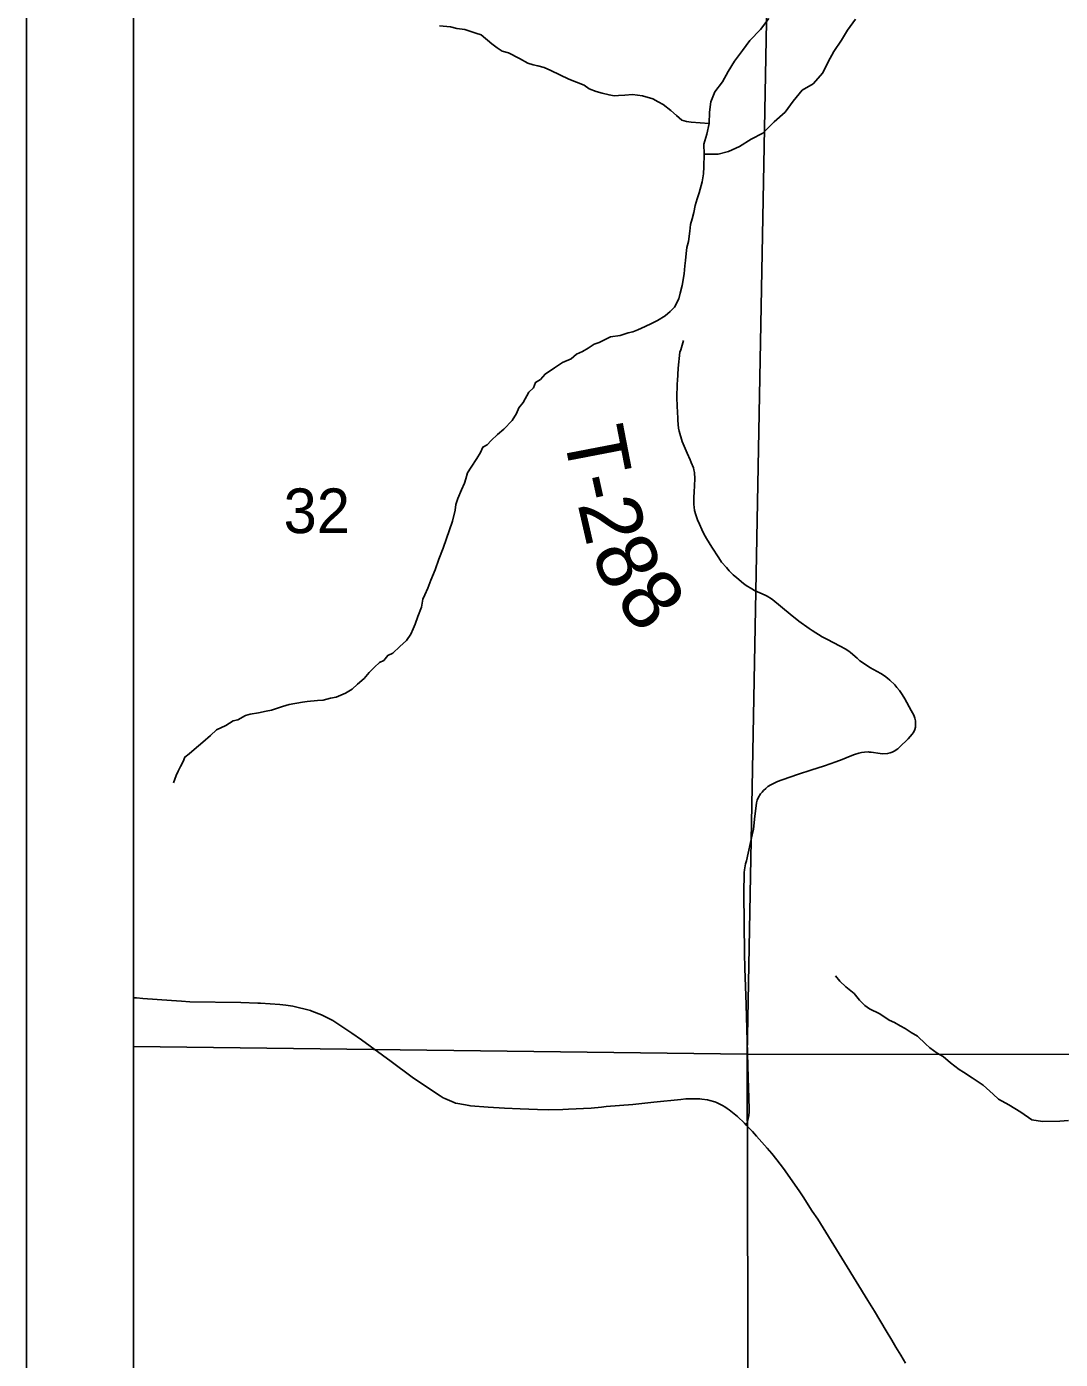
# Model space of a CAD drawing. Extents: x 0 to 34, y 0 to 22.
# Drawn here: x 18.5 to 19.467, y 15.38 to 16.628 of the extents above; entities that cross this region are included whole.
import ezdxf

# ---------------------------------------------------------------- set-up
doc = ezdxf.new("R2010")
doc.units = 0
for name, color, linetype in [('GM_X_Corporation', 7, 'Continuous'), ('GM_X_County_Road', 7, 'Continuous'), ('GM_X_Major_Lake', 7, 'Continuous'), ('GM_X_Minor_River', 7, 'Continuous'), ('GM_X_Section_Text', 7, 'Continuous'), ('GM_X_Township_Road', 7, 'Continuous'), ('GM_X_Township_Road_Text', 7, 'Continuous'), ('SH_Data', 7, 'Continuous')]:
    doc.layers.add(name, color=color, linetype=linetype)

msp = doc.modelspace()

# ---------------------------------------------------------------- linework, layer by layer
at = {"layer": 'GM_X_Corporation'}
for points in [[(18.6, 19.2331), (18.6, 14.6606), (18.9216, 14.6592), (19.4007, 14.6554), (19.8855, 14.6528), (20.2016, 14.6512), (20.203, 14.81), (20.1987, 15.2691), (20.2208, 16.9558), (20.2471, 18.8539), (20.254, 19.2058), (20.065, 19.208), (18.9898, 19.2261)], [(18.6, 16.7037), (18.6, 15.673), (19.1743, 15.6658), (19.1937, 16.6992)], [(19.1937, 16.6992), (20.2179, 16.6698), (20.1931, 15.6647), (19.1743, 15.6658)], [(18.6, 15.673), (18.6, 14.6612), (19.1768, 14.6588), (19.1743, 15.6658)], [(20.1931, 15.6647), (20.2028, 14.6536), (19.1768, 14.6588), (19.1743, 15.6658)]]:
    msp.add_lwpolyline(points, close=True, dxfattribs=at)
at = {"layer": 'GM_X_County_Road'}
msp.add_lwpolyline([(18.6, 15.7185), (18.6029, 15.7184), (18.6087, 15.7179), (18.6357, 15.7158), (18.645, 15.7152), (18.6528, 15.7148), (18.7003, 15.7142), (18.7165, 15.7135), (18.7187, 15.7134), (18.7368, 15.7121), (18.7426, 15.7115), (18.7469, 15.711), (18.749, 15.7105), (18.7656, 15.7065), (18.7669, 15.706), (18.7759, 15.7026), (18.7817, 15.6996), (18.7865, 15.6971), (18.7883, 15.6959), (18.8043, 15.6853), (18.8133, 15.679), (18.8411, 15.6589), (18.8609, 15.6443), (18.8677, 15.6395), (18.887, 15.6266), (18.8898, 15.6249), (18.8915, 15.6241), (18.9, 15.6205), (18.9014, 15.6199), (18.9036, 15.6195), (18.914, 15.6176), (18.9155, 15.6174), (18.9318, 15.6161), (18.9472, 15.6152), (18.962, 15.6145), (18.9781, 15.6139), (18.9888, 15.6137), (19.0018, 15.6138), (19.0072, 15.6141), (19.0282, 15.6152), (19.038, 15.6161), (19.0425, 15.6166), (19.0672, 15.6187), (19.0869, 15.6209), (19.1122, 15.6234), (19.1169, 15.6238), (19.1249, 15.624), (19.1301, 15.624), (19.1319, 15.6237), (19.1371, 15.623), (19.1393, 15.6224), (19.144, 15.6211), (19.1455, 15.6205), (19.1512, 15.6177), (19.1533, 15.6164), (19.1557, 15.6148), (19.1575, 15.6135), (19.1652, 15.6072), (19.1717, 15.6012), (19.1734, 15.5992), (19.1756, 15.5972), (19.1792, 15.5934), (19.1832, 15.5891), (19.1931, 15.5777), (19.1974, 15.5726), (19.202, 15.5667), (19.2083, 15.5586), (19.2231, 15.5377), (19.2268, 15.5321), (19.2352, 15.5188), (19.2403, 15.5112), (19.2655, 15.4706), (19.2872, 15.4352), (19.2934, 15.4251), (19.3045, 15.4066), (19.3096, 15.3979), (19.3136, 15.3913), (19.318, 15.3838), (19.3224, 15.3765)], dxfattribs=at)
at = {"layer": 'GM_X_Major_Lake'}
msp.add_lwpolyline([(19.1947, 16.6352), (19.1868, 16.6249), (19.1769, 16.6147), (19.1701, 16.6052), (19.1626, 16.5953), (19.1565, 16.5854), (19.1512, 16.576), (19.144, 16.5665), (19.1402, 16.557), (19.1391, 16.5475), (19.1387, 16.5369), (19.1365, 16.527), (19.1338, 16.5175), (19.1342, 16.508), (19.1471, 16.508), (19.1569, 16.5107), (19.1671, 16.5153), (19.1781, 16.5221), (19.1891, 16.5278), (19.1997, 16.5384), (19.2099, 16.5476), (19.2175, 16.5578), (19.2258, 16.5681), (19.236, 16.5741), (19.2451, 16.5844), (19.25, 16.5947), (19.2553, 16.6041), (19.2625, 16.6148), (19.2681, 16.6243), (19.2757, 16.6345)], dxfattribs=at)
at = {"layer": 'GM_X_Minor_River'}
for points in [[(19.1387, 16.5369), (19.1219, 16.5381), (19.1174, 16.5388), (19.1132, 16.5399), (19.1082, 16.5444), (19.1029, 16.5489), (19.0956, 16.5545), (19.091, 16.5571), (19.086, 16.56), (19.0765, 16.5626), (19.0671, 16.5639), (19.0599, 16.5635), (19.0538, 16.563), (19.0497, 16.5629), (19.0451, 16.5636), (19.0386, 16.5654), (19.033, 16.5669), (19.0265, 16.5694), (19.0219, 16.5728), (19.0074, 16.5783), (18.9906, 16.5864), (18.9842, 16.5893), (18.9785, 16.5908), (18.9739, 16.5919), (18.969, 16.5933), (18.9613, 16.5978), (18.951, 16.6029), (18.945, 16.6047), (18.9404, 16.6077), (18.9354, 16.6115), (18.9254, 16.6197), (18.9205, 16.6215), (18.9102, 16.6248), (18.9026, 16.6258), (18.8966, 16.6272), (18.8863, 16.6282)], [(19.1342, 16.508), (19.1339, 16.4964), (19.1336, 16.4896), (19.1322, 16.4823), (19.1293, 16.472), (19.1275, 16.4662), (19.1257, 16.4601), (19.1243, 16.4536), (19.1229, 16.4475), (19.1214, 16.4422), (19.1208, 16.4361), (19.1194, 16.4265), (19.1179, 16.4208), (19.1173, 16.4151), (19.1166, 16.4086), (19.1159, 16.4036), (19.1153, 16.396), (19.1135, 16.3853), (19.1117, 16.378), (19.1103, 16.3727), (19.1062, 16.365), (19.1021, 16.3608), (19.0977, 16.3569), (19.0905, 16.3526), (19.0849, 16.3495), (19.0789, 16.3467), (19.0721, 16.3436), (19.0672, 16.342), (19.0631, 16.3408), (19.0555, 16.3384), (19.0465, 16.3371), (19.0419, 16.3351), (19.0359, 16.332), (19.031, 16.3304), (19.0254, 16.3265), (19.0201, 16.3234), (19.0145, 16.321), (19.0096, 16.3167), (19.0014, 16.3132), (18.9939, 16.3081), (18.9852, 16.3023), (18.9808, 16.2972), (18.9763, 16.2945), (18.9744, 16.2895), (18.97, 16.2853), (18.9648, 16.2757), (18.9607, 16.2707), (18.9585, 16.2653), (18.9544, 16.2588), (18.9466, 16.2507), (18.9406, 16.2456), (18.9346, 16.2402), (18.9309, 16.236), (18.9268, 16.234), (18.9246, 16.229), (18.9212, 16.2232), (18.9161, 16.2152), (18.9127, 16.2098), (18.9109, 16.2044), (18.9098, 16.2002), (18.9069, 16.1941), (18.9036, 16.1857), (18.9018, 16.1803), (18.9011, 16.175), (18.8986, 16.1646), (18.8899, 16.1394), (18.8859, 16.129), (18.8822, 16.1191), (18.8782, 16.1095), (18.8753, 16.1018), (18.8727, 16.0957), (18.8709, 16.0915), (18.8695, 16.0842), (18.8662, 16.0754), (18.8636, 16.0681), (18.8618, 16.0639), (18.8596, 16.0589), (18.8555, 16.0528), (18.8492, 16.0474), (18.8428, 16.0412), (18.8379, 16.0388), (18.8342, 16.0342), (18.8301, 16.0322), (18.8256, 16.028), (18.8207, 16.0229), (18.8159, 16.0175), (18.8095, 16.0121), (18.8047, 16.0075), (18.7983, 16.0035), (18.7896, 16), (18.7843, 15.9988), (18.7776, 15.9971), (18.7723, 15.9967), (18.7624, 15.9958), (18.7583, 15.9953), (18.7458, 15.9929), (18.7394, 15.9912), (18.7292, 15.9877), (18.7243, 15.9868), (18.7171, 15.9852)], [(18.7171, 15.9852), (18.7092, 15.9839), (18.7047, 15.9827), (18.6976, 15.9788), (18.6934, 15.9776), (18.6863, 15.9733), (18.6776, 15.9694), (18.672, 15.9639), (18.6649, 15.9577), (18.6567, 15.9508), (18.6522, 15.9469), (18.6481, 15.9438), (18.6466, 15.9396), (18.644, 15.9349), (18.6418, 15.9307), (18.64, 15.9265), (18.6374, 15.9196)], [(19.4751, 15.6036), (19.4668, 15.6031), (19.4509, 15.6028), (19.4467, 15.6032), (19.4407, 15.6042), (19.4303, 15.6113), (19.4193, 15.6184), (19.4094, 15.6235), (19.4047, 15.6284), (19.3952, 15.6367), (19.3848, 15.6437), (19.3768, 15.6489), (19.3726, 15.6512), (19.3646, 15.6575), (19.3577, 15.6635), (19.352, 15.6665), (19.3454, 15.6717), (19.3412, 15.6755), (19.3336, 15.6826), (19.3278, 15.6859), (19.3221, 15.6896), (19.3175, 15.6922), (19.3122, 15.6952), (19.3072, 15.6974), (19.2984, 15.7034), (19.2889, 15.7082), (19.2843, 15.7112), (19.2793, 15.7164), (19.2743, 15.7224), (19.2667, 15.7288), (19.2609, 15.734), (19.2571, 15.7389)]]:
    msp.add_lwpolyline(points, dxfattribs=at)
at = {"layer": 'GM_X_Township_Road'}
for points in [[(19.2887, 15.9485), (19.2904, 15.9484), (19.2989, 15.9471), (19.3013, 15.9469), (19.3058, 15.9471), (19.3083, 15.9477), (19.3101, 15.9484), (19.3119, 15.9494), (19.3152, 15.9516), (19.3169, 15.9531), (19.325, 15.9609), (19.3269, 15.9629), (19.3287, 15.9651), (19.3296, 15.9665), (19.3305, 15.9679), (19.3313, 15.9697), (19.3318, 15.9717), (19.332, 15.9737), (19.3318, 15.9776), (19.3313, 15.9801), (19.3302, 15.9829), (19.3279, 15.9873), (19.3219, 15.9983), (19.3195, 16.0024), (19.3169, 16.0062), (19.3143, 16.009), (19.3124, 16.0113), (19.3078, 16.0158), (19.3055, 16.0177), (19.3028, 16.0198), (19.2993, 16.022), (19.289, 16.0276), (19.2859, 16.0297), (19.2799, 16.034), (19.2772, 16.0364), (19.2711, 16.0417), (19.2695, 16.0429), (19.2661, 16.045), (19.2614, 16.0475), (19.2489, 16.0541), (19.2446, 16.0565), (19.235, 16.0622), (19.2323, 16.064), (19.2228, 16.0711), (19.2146, 16.0776), (19.1983, 16.0911), (19.197, 16.092), (19.1931, 16.0944), (19.1911, 16.0954), (19.1813, 16.0998), (19.1787, 16.1012), (19.1735, 16.1044), (19.1709, 16.1063), (19.1645, 16.1115), (19.1613, 16.1143), (19.1576, 16.118), (19.1549, 16.1211), (19.1503, 16.1263), (19.1477, 16.1304), (19.1412, 16.1403), (19.1364, 16.1483), (19.1337, 16.1527), (19.1318, 16.1568), (19.1297, 16.1617), (19.1278, 16.1659), (19.1262, 16.1706), (19.125, 16.1746), (19.1247, 16.1776), (19.1244, 16.1801), (19.1243, 16.1828), (19.1244, 16.1871), (19.1247, 16.1919), (19.1252, 16.2044), (19.1249, 16.2101), (19.1244, 16.2126), (19.124, 16.2145), (19.122, 16.2196), (19.121, 16.222), (19.1181, 16.2283), (19.1144, 16.2369), (19.1135, 16.2393), (19.1106, 16.249), (19.1102, 16.2516), (19.1094, 16.2588), (19.1093, 16.2615), (19.109, 16.2659), (19.1087, 16.2729), (19.1084, 16.2799), (19.1088, 16.2934), (19.109, 16.2959), (19.1097, 16.3078), (19.1114, 16.3227), (19.1122, 16.3251), (19.1147, 16.3336)], [(19.1734, 15.5992), (19.1739, 15.6004), (19.1742, 15.6015), (19.1746, 15.6027), (19.1753, 15.6054), (19.1758, 15.6083), (19.1761, 15.6117), (19.1762, 15.6139), (19.1758, 15.6247), (19.1752, 15.6437), (19.1744, 15.678), (19.1733, 15.7123), (19.1722, 15.7458), (19.1719, 15.7602), (19.1713, 15.8162), (19.1716, 15.8359), (19.1718, 15.8383), (19.1729, 15.844), (19.1737, 15.8468), (19.1791, 15.8709), (19.1802, 15.8759), (19.1813, 15.8856), (19.1832, 15.901), (19.1837, 15.9034), (19.1846, 15.9058), (19.1869, 15.9094), (19.1882, 15.9111), (19.1897, 15.9126), (19.1918, 15.9145), (19.1936, 15.9161), (19.1965, 15.9179), (19.1991, 15.9192), (19.2026, 15.9209), (19.207, 15.9226), (19.2225, 15.9277), (19.2338, 15.9314), (19.2468, 15.9357), (19.2572, 15.9394), (19.2632, 15.9415), (19.2707, 15.9445), (19.2748, 15.9462), (19.2789, 15.9476), (19.2814, 15.948), (19.284, 15.9483), (19.2879, 15.9486), (19.2887, 15.9485)]]:
    msp.add_lwpolyline(points, dxfattribs=at)
at = {"layer": 'SH_Data'}
for points in [[(18.5, 20.5), (25.5, 20.5), (25.5, 13.5), (18.5, 13.5)], [(18.6, 20.4), (25.4, 20.4), (25.4, 13.6), (18.6, 13.6)]]:
    msp.add_lwpolyline(points, close=True, dxfattribs=at)

# ---------------------------------------------------------------- texts
at = {"layer": 'GM_X_Section_Text'}
msp.add_text('32', height=0.04186, rotation=0, dxfattribs=at).set_placement((18.7404, 16.1534))
at = {"layer": 'GM_X_Township_Road_Text'}
for s, rotation, p in [('T', 280.9216, (19.0019, 16.2475)), ('-', 282.4423, (19.0103, 16.2042)), ('2', 282.9819, (19.0155, 16.1808)), ('8', 294.5801, (19.0274, 16.1349)), ('8', 308.4406, (19.0497, 16.0903))]:
    msp.add_text(s, height=0.0568, rotation=rotation, dxfattribs=at).set_placement(p)

doc.saveas('drawing.dxf')
